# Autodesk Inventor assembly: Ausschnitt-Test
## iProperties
Created: 2007-09
Part Number: Ausschnitt-Test
Document SubType Name: Assembly
Designer: WH
Mass: 4368.22 g
Surface Area: 3194.65 cm^2
Volume: 4368.22 cm^3
Density: 1 g/cm^3
Author: WH
